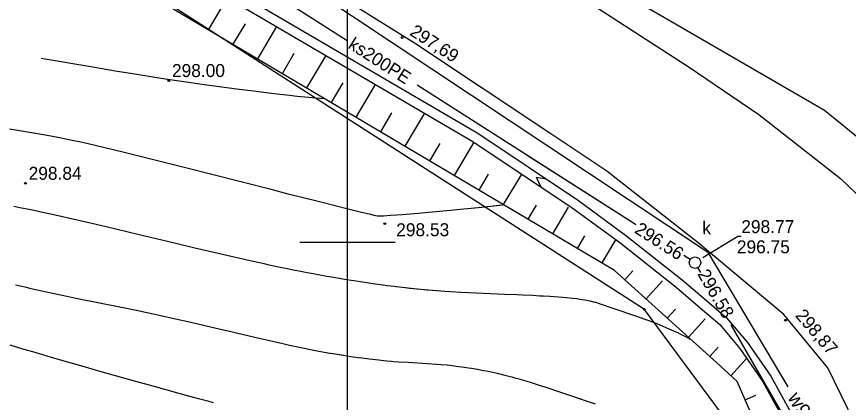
# Model space of a CAD drawing. Extents: x 7477803 to 7478145, y 5500698 to 5500984.
# Drawn here: x 7477982.63 to 7478026.29, y 5500841.6 to 5500861.83 of the extents above; entities that cross this region are included whole.
import ezdxf

# ---------------------------------------------------------------- set-up
doc = ezdxf.new("R2010")
doc.units = 0
for name, color, linetype in [('203-Punkt załamania granicy działki nie stabilizowany', 7, 'Continuous'), ('eNN', 7, 'Continuous'), ('gr_dzialki', 7, 'Continuous'), ('gr_klasy', 7, 'Continuous'), ('jezdnia', 7, 'Continuous'), ('k', 7, 'Continuous'), ('k_elem_naziemne', 7, 'Continuous'), ('k_opis', 7, 'Continuous'), ('k_rzedne', 7, 'Continuous'), ('pkt_wys', 7, 'Continuous'), ('robocza49', 7, 'Continuous'), ('rowy', 7, 'Continuous'), ('skarp_wypel', 7, 'Continuous'), ('skarpa_gora', 7, 'Continuous'), ('w', 7, 'Continuous'), ('w_opis', 7, 'Continuous'), ('warst_ciagla', 7, 'Continuous'), ('warst_pogrub', 7, 'Continuous'), ('warst_przeryw', 7, 'Continuous')]:
    doc.layers.add(name, color=color, linetype=linetype)

# ---------------------------------------------------------------- blocks, each defined once
blk = doc.blocks.new('203')
blk.add_circle((0, 0), 0.045)
blk = doc.blocks.new('506_5_1')
at = {"layer": 'k_elem_naziemne'}
blk.add_circle((0, 0), 0.3, dxfattribs=at)
blk = doc.blocks.new('801_3')
at = {"layer": 'pkt_wys'}
blk.add_circle((0, 0), 0.045, dxfattribs=at)
blk.add_circle((0, 0), 0.045, dxfattribs=at)
blk = doc.blocks.new('801_5_2')
at = {"layer": 'pkt_wys'}
blk.add_circle((0, 0), 0.05, dxfattribs=at)
blk.add_circle((0, 0), 0.05, dxfattribs=at)

msp = doc.modelspace()

# ---------------------------------------------------------------- linework, layer by layer
at = {"layer": 'eNN'}
msp.add_lwpolyline([(7478044.292, 5500829.332), (7478043.979, 5500830.08), (7478036.967, 5500842.126), (7478033.374, 5500847.92), (7478030.266, 5500851.792), (7478027.179, 5500855.154), (7478025.031, 5500856.9), (7478008.369, 5500866.572), (7477997.07, 5500873.297), (7477990.438, 5500877.31), (7477980.374, 5500883.358), (7477966.627, 5500891.122), (7477956.111, 5500897.36), (7477948.099, 5500902.324), (7477944.454, 5500904.573)], dxfattribs=at)
at = {"layer": 'gr_dzialki'}
for points in [[(7478015.58, 5500846.47), (7477983.69, 5500866.96)], [(7478021.72, 5500838.18), (7478015.58, 5500846.47)]]:
    msp.add_lwpolyline(points, dxfattribs=at)
at = {"layer": 'gr_klasy'}
for points in [[(7478015.58, 5500846.47), (7477983.69, 5500866.96)], [(7478021.72, 5500838.18), (7478015.58, 5500846.47)]]:
    msp.add_lwpolyline(points, dxfattribs=at)
at = {"layer": 'jezdnia'}
for points in [[(7478010.61, 5500855.711), (7478003.516, 5500860.43), (7477987.535, 5500870.412)], [(7478012.783, 5500862.5), (7478017.927, 5500859.186), (7478021.58, 5500856.7), (7478025.873, 5500853.334), (7478028.356, 5500850.967), (7478030.699, 5500848.349), (7478032.422, 5500845.441), (7478033.114, 5500843.932), (7478033.826, 5500841.963), (7478034.518, 5500839.904), (7478035.522, 5500835.985), (7478035.876, 5500832.755), (7478035.757, 5500831.475), (7478035.341, 5500827.995), (7478034.495, 5500824.894), (7478032.649, 5500820.712), (7478031.642, 5500818.53)], [(7478008.149, 5500811.845), (7478011.769, 5500811.909), (7478014.098, 5500812.451), (7478017.047, 5500813.895), (7478021.153, 5500817.039), (7478024.239, 5500820.732), (7478026.136, 5500823.914), (7478027.522, 5500827.266), (7478028.159, 5500830.207), (7478028.284, 5500834.367), (7478027.822, 5500836.806), (7478026.257, 5500841.255), (7478025.204, 5500843.403), (7478022.901, 5500846.211), (7478018.407, 5500849.956), (7478013.603, 5500853.721), (7478010.61, 5500855.711)]]:
    msp.add_lwpolyline(points, dxfattribs=at)
at = {"layer": 'k'}
for p, q in [((7478018.542, 5500848.401), (7478018.389, 5500848.666)), ((7478018.464, 5500848.536), (7478018.389, 5500848.666)), ((7478021.173, 5500843.859), (7478020.132, 5500845.657)), ((7478024.88, 5500837.459), (7478020.15, 5500845.626))]:
    msp.add_line(p, q, dxfattribs=at)
for points in [[(7477999.978, 5500860.567), (7477987.079, 5500868.79)], [(7478015.054, 5500850.956), (7478003.646, 5500858.229)], [(7478015.054, 5500850.956), (7478009.436, 5500854.538)], [(7478015.128, 5500850.909), (7478015.058, 5500850.953)], [(7478017.985, 5500849.087), (7478017.658, 5500849.296)], [(7478017.985, 5500849.087), (7478017.722, 5500849.255)]]:
    msp.add_lwpolyline(points, dxfattribs=at)
at = {"layer": 'k_rzedne'}
msp.add_lwpolyline([(7478020.666, 5500850.293), (7478020.486, 5500850.292), (7478018.654, 5500849.176)], dxfattribs=at)
at = {"layer": 'robocza49'}
for p, q in [((7478000, 5500750), (7478000, 5500973.047)), ((7477997.5, 5500850), (7478000, 5500850)), ((7478000, 5500850), (7478002.5, 5500850))]:
    msp.add_line(p, q, dxfattribs=at)
at = {"layer": 'rowy'}
for points in [[(7477993.882, 5500863.302), (7478006.843, 5500855.712), (7478012.127, 5500852.184), (7478014.592, 5500850.374), (7478017.571, 5500848.032), (7478018.72, 5500847.044), (7478019.889, 5500846.025), (7478020.984, 5500844.732), (7478022.21, 5500842.975), (7478023.266, 5500841.06)], [(7477993.629, 5500862.871), (7478006.577, 5500855.288), (7478011.84, 5500851.774), (7478014.289, 5500849.976), (7478017.253, 5500847.646), (7478018.393, 5500846.666), (7478019.532, 5500845.673), (7478020.588, 5500844.427), (7478021.784, 5500842.711), (7478022.816, 5500840.841)], [(7478010.445, 5500853.307), (7478009.897, 5500853.386), (7478010.167, 5500852.891)]]:
    msp.add_lwpolyline(points, dxfattribs=at)
at = {"layer": 'skarp_wypel'}
for p, q in [((7477992.709, 5500861.145), (7477993.705, 5500862.826)), ((7477996.548, 5500861.74), (7477996.553, 5500861.749)), ((7477993.999, 5500860.381), (7477994.636, 5500861.456)), ((7477995.29, 5500859.616), (7477996.293, 5500861.31)), ((7477996.58, 5500858.852), (7477997.207, 5500859.909)), ((7477997.871, 5500858.087), (7477998.882, 5500859.794)), ((7477999.161, 5500857.322), (7477999.777, 5500858.363)), ((7478000.452, 5500856.558), (7478001.471, 5500858.278)), ((7478001.742, 5500855.793), (7478002.333, 5500856.79)), ((7478003.032, 5500855.028), (7478004.06, 5500856.762)), ((7478005.613, 5500853.499), (7478006.644, 5500855.239)), ((7478004.323, 5500854.264), (7478004.863, 5500855.176)), ((7478006.904, 5500852.734), (7478007.394, 5500853.562)), ((7478008.194, 5500851.97), (7478009.125, 5500853.54)), ((7478009.485, 5500851.205), (7478009.925, 5500851.948)), ((7478010.775, 5500850.441), (7478011.605, 5500851.841)), ((7478012.066, 5500849.676), (7478012.456, 5500850.334)), ((7478013.356, 5500848.911), (7478014.074, 5500850.123)), ((7478014.558, 5500848.027), (7478014.979, 5500848.491)), ((7478015.671, 5500847.02), (7478016.525, 5500847.964)), ((7478016.783, 5500846.014), (7478017.217, 5500846.493)), ((7478017.895, 5500845.008), (7478018.776, 5500845.981)), ((7478019.008, 5500844.001), (7478019.455, 5500844.495)), ((7478020.12, 5500842.995), (7478020.948, 5500843.91)), ((7478020.875, 5500843.829), (7478020.948, 5500843.91)), ((7478020.869, 5500841.727), (7478021.423, 5500841.969))]:
    msp.add_line(p, q, dxfattribs=at)
at = {"layer": 'skarpa_gora'}
for points in [[(7478019.361, 5500843.679), (7478014.009, 5500848.521), (7477985, 5500865.71), (7477963.897, 5500877.826), (7477945.275, 5500888.626), (7477927.783, 5500899.247), (7477912.023, 5500908.9), (7477901.238, 5500913.008)], [(7478024.174, 5500834.162), (7478020.445, 5500842.698), (7478019.361, 5500843.679)]]:
    msp.add_lwpolyline(points, dxfattribs=at)
at = {"layer": 'w'}
msp.add_lwpolyline([(7478023.125, 5500842.409), (7478018.943, 5500849.443), (7477996.094, 5500864.625), (7477987.395, 5500870.305)], dxfattribs=at)
at = {"layer": 'warst_ciagla'}
for points in [[(7477998.803, 5500857.513), (7477998.521, 5500857.535), (7477997.944, 5500857.586), (7477997.354, 5500857.646), (7477996.955, 5500857.69), (7477996.148, 5500857.785), (7477994.926, 5500857.935), (7477994.314, 5500858.012), (7477993.397, 5500858.133), (7477992.486, 5500858.257), (7477991.28, 5500858.428), (7477990.681, 5500858.517), (7477989.881, 5500858.639), (7477989.472, 5500858.702), (7477988.836, 5500858.804), (7477987.801, 5500858.974), (7477986.637, 5500859.172), (7477983.919, 5500859.642)], [(7478018.003, 5500844.893), (7478017.839, 5500844.984), (7478017.726, 5500845.044), (7478017.492, 5500845.163), (7478017.372, 5500845.221), (7478017.129, 5500845.335), (7478016.886, 5500845.444), (7478016.725, 5500845.514), (7478016.412, 5500845.644), (7478016.245, 5500845.711), (7478015.926, 5500845.833), (7478015.629, 5500845.941), (7478015.085, 5500846.13), (7478014.04, 5500846.486), (7478013.23, 5500846.761), (7478013.03, 5500846.827), (7478012.927, 5500846.857), (7478012.758, 5500846.901), (7478012.63, 5500846.929), (7478012.56, 5500846.943), (7478012.446, 5500846.963), (7478012.319, 5500846.982), (7478012.13, 5500847.008), (7478012.027, 5500847.021), (7478011.805, 5500847.045), (7478011.474, 5500847.077), (7478011.294, 5500847.093), (7478010.851, 5500847.127), (7478010.611, 5500847.143), (7478010.272, 5500847.165), (7478010.094, 5500847.175), (7478009.721, 5500847.196), (7478009.189, 5500847.222), (7478008.908, 5500847.235), (7478008.239, 5500847.263), (7478006.757, 5500847.32), (7478005.953, 5500847.358), (7478005.396, 5500847.391), (7478005.112, 5500847.409), (7478004.679, 5500847.441), (7478004.238, 5500847.478), (7478003.64, 5500847.534), (7478003.336, 5500847.566), (7478002.718, 5500847.635), (7478002.439, 5500847.669), (7478002.063, 5500847.717), (7478001.873, 5500847.742), (7478001.442, 5500847.801), (7478001.115, 5500847.848), (7478000.674, 5500847.914), (7478000.451, 5500847.948), (7477999.945, 5500848.029), (7477999.258, 5500848.145), (7477998.909, 5500848.206), (7477998.203, 5500848.335), (7477997.885, 5500848.395), (7477997.456, 5500848.478), (7477997.24, 5500848.521), (7477996.75, 5500848.619), (7477996.379, 5500848.696), (7477995.879, 5500848.801), (7477995.627, 5500848.855), (7477995.054, 5500848.981), (7477994.67, 5500849.066), (7477993.899, 5500849.242), (7477992.747, 5500849.51), (7477991.993, 5500849.689), (7477990.548, 5500850.034), (7477989.064, 5500850.388), (7477987.338, 5500850.797), (7477986.582, 5500850.974), (7477985.584, 5500851.206), (7477984.505, 5500851.451), (7477984.073, 5500851.547), (7477983.552, 5500851.658), (7477983.271, 5500851.715), (7477982.8, 5500851.807), (7477982.478, 5500851.868)], [(7478008.147, 5500851.946), (7478007.678, 5500851.888), (7478007.352, 5500851.851), (7478006.678, 5500851.781)], [(7478018.003, 5500844.893), (7478017.839, 5500844.984), (7478017.726, 5500845.044), (7478017.492, 5500845.163), (7478017.372, 5500845.221), (7478017.129, 5500845.335), (7478016.886, 5500845.444), (7478016.725, 5500845.514), (7478016.412, 5500845.644), (7478016.245, 5500845.711), (7478015.926, 5500845.833), (7478015.629, 5500845.941), (7478015.085, 5500846.13), (7478014.04, 5500846.486), (7478013.23, 5500846.761), (7478013.03, 5500846.827), (7478012.927, 5500846.857), (7478012.758, 5500846.901), (7478012.63, 5500846.929), (7478012.56, 5500846.943), (7478012.446, 5500846.963), (7478012.319, 5500846.982), (7478012.13, 5500847.008), (7478012.027, 5500847.021), (7478011.805, 5500847.045), (7478011.474, 5500847.077), (7478011.294, 5500847.093), (7478010.851, 5500847.127), (7478010.611, 5500847.143), (7478010.272, 5500847.165), (7478010.094, 5500847.175), (7478009.721, 5500847.196), (7478009.189, 5500847.222), (7478008.908, 5500847.235), (7478008.239, 5500847.263), (7478006.757, 5500847.32), (7478005.953, 5500847.358), (7478005.396, 5500847.391), (7478005.112, 5500847.409), (7478004.679, 5500847.441), (7478004.45, 5500847.46), (7478004.142, 5500847.486), (7478003.987, 5500847.501), (7478003.674, 5500847.531), (7478003.25, 5500847.575), (7478003.037, 5500847.599), (7478002.549, 5500847.656)]]:
    msp.add_lwpolyline(points, dxfattribs=at)
at = {"layer": 'warst_pogrub'}
msp.add_lwpolyline([(7477992.967, 5500841.575), (7477992.736, 5500841.636), (7477992.173, 5500841.787), (7477991.215, 5500842.048), (7477989.725, 5500842.459), (7477988.888, 5500842.693), (7477987.067, 5500843.206), (7477986.128, 5500843.473), (7477984.755, 5500843.868), (7477983.488, 5500844.239), (7477982.963, 5500844.395), (7477982.3, 5500844.594)], dxfattribs=at)
at = {"layer": 'warst_przeryw'}
for points in [[(7478008.147, 5500851.946), (7478007.936, 5500851.919), (7478007.5, 5500851.868), (7478007.047, 5500851.819), (7478006.11, 5500851.726), (7478005.403, 5500851.66), (7478004.081, 5500851.541), (7478003.513, 5500851.492), (7478002.868, 5500851.439), (7478002.595, 5500851.418), (7478002.246, 5500851.393), (7478001.894, 5500851.372), (7478001.766, 5500851.366), (7478001.678, 5500851.365), (7478001.637, 5500851.366), (7478001.576, 5500851.371), (7478001.466, 5500851.389), (7478001.397, 5500851.403), (7478001.214, 5500851.445), (7478000.795, 5500851.545), (7477999.955, 5500851.753), (7477999.414, 5500851.888), (7477998.452, 5500852.13), (7477996.887, 5500852.526), (7477995.984, 5500852.756), (7477992.94, 5500853.53), (7477991.42, 5500853.915), (7477990.03, 5500854.264), (7477988.408, 5500854.665), (7477987.696, 5500854.838), (7477986.751, 5500855.063), (7477986.379, 5500855.15), (7477985.928, 5500855.254), (7477985.722, 5500855.3), (7477985.306, 5500855.391), (7477984.798, 5500855.496), (7477984.52, 5500855.549), (7477984.046, 5500855.633), (7477983.098, 5500855.792), (7477982.259, 5500855.928)], [(7477982.57, 5500847.769), (7477982.811, 5500847.71), (7477983.144, 5500847.631), (7477983.316, 5500847.591), (7477983.717, 5500847.499), (7477984.352, 5500847.358), (7477984.352, 5500847.358), (7477985.263, 5500847.165), (7477985.745, 5500847.066), (7477988.129, 5500846.587), (7477988.993, 5500846.407), (7477990.195, 5500846.149), (7477990.817, 5500846.013), (7477991.778, 5500845.797), (7477993.109, 5500845.492), (7477993.796, 5500845.331), (7477995.204, 5500844.999), (7477995.912, 5500844.835), (7477996.612, 5500844.677), (7477996.957, 5500844.601), (7477997.299, 5500844.528), (7477997.746, 5500844.436), (7477997.967, 5500844.392), (7477998.404, 5500844.308), (7477998.973, 5500844.203), (7477999.252, 5500844.155), (7477999.867, 5500844.054), (7478000.169, 5500844.008), (7478000.563, 5500843.952), (7478000.757, 5500843.925), (7478001.14, 5500843.877), (7478001.638, 5500843.82), (7478001.882, 5500843.795), (7478002.062, 5500843.778), (7478002.3, 5500843.758), (7478002.417, 5500843.748), (7478002.679, 5500843.729), (7478003.189, 5500843.697), (7478004.177, 5500843.641), (7478004.662, 5500843.608), (7478004.903, 5500843.588), (7478005.224, 5500843.557), (7478005.384, 5500843.539), (7478005.704, 5500843.501), (7478006.13, 5500843.443), (7478006.342, 5500843.411), (7478006.501, 5500843.386), (7478006.713, 5500843.35), (7478006.819, 5500843.331), (7478007.056, 5500843.288), (7478007.372, 5500843.225), (7478007.53, 5500843.192), (7478007.845, 5500843.123), (7478008.264, 5500843.023), (7478008.473, 5500842.97), (7478008.63, 5500842.929), (7478008.838, 5500842.872), (7478008.943, 5500842.843), (7478009.177, 5500842.776), (7478009.643, 5500842.635), (7478010.106, 5500842.487), (7478010.412, 5500842.387), (7478011.019, 5500842.184), (7478012.285, 5500841.758)], [(7477999.077, 5500844.185), (7477999.343, 5500844.139), (7477999.694, 5500844.081), (7477999.867, 5500844.054), (7478000.169, 5500844.008), (7478000.563, 5500843.952), (7478000.757, 5500843.925), (7478001.14, 5500843.877), (7478001.638, 5500843.82), (7478001.882, 5500843.795), (7478002.062, 5500843.778), (7478002.3, 5500843.758), (7478002.417, 5500843.748), (7478002.679, 5500843.729), (7478003.189, 5500843.697), (7478004.177, 5500843.641), (7478004.662, 5500843.608), (7478004.903, 5500843.588), (7478005.224, 5500843.557), (7478005.384, 5500843.539), (7478005.704, 5500843.501), (7478006.13, 5500843.443), (7478006.342, 5500843.411), (7478006.501, 5500843.386), (7478006.713, 5500843.35), (7478006.819, 5500843.331), (7478007.056, 5500843.288), (7478007.372, 5500843.225), (7478007.53, 5500843.192), (7478007.845, 5500843.123), (7478008.264, 5500843.023), (7478008.473, 5500842.97), (7478008.63, 5500842.929), (7478008.838, 5500842.872), (7478008.943, 5500842.843), (7478009.177, 5500842.776), (7478009.643, 5500842.635), (7478010.106, 5500842.487), (7478010.412, 5500842.387), (7478011.019, 5500842.184), (7478012.992, 5500841.519)]]:
    msp.add_lwpolyline(points, dxfattribs=at)

# ---------------------------------------------------------------- block references
at = {"layer": '203-Punkt załamania granicy działki nie stabilizowany'}
msp.add_blockref('203', (7478015.58, 5500846.47), dxfattribs=at)
at = {"layer": 'k_elem_naziemne', "rotation": 0.0626175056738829}
msp.add_blockref('506_5_1', (7478018.238, 5500848.926), dxfattribs=at)
at = {"layer": 'pkt_wys', "rotation": 0.0626175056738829}
for name, p in [('801_5_2', (7478002.875, 5500860.739)), ('801_3', (7477990.618, 5500858.476)), ('801_3', (7477983.094, 5500853.087)), ('801_3', (7478001.956, 5500850.968)), ('801_5_2', (7478022.992, 5500845.901))]:
    msp.add_blockref(name, p, dxfattribs=at)

# ---------------------------------------------------------------- texts
at = {"layer": 'k_elem_naziemne'}
msp.add_text('k', height=0.68, rotation=0.0626, dxfattribs=at).set_placement((7478018.621, 5500850.411))
at = {"layer": 'k_opis'}
msp.add_text('ks200PE', height=0.68, rotation=327.4817, dxfattribs=at).set_placement((7477999.978, 5500860.21))
at = {"layer": 'k_rzedne'}
for s, rotation, p in [('296.56', 327.4817, (7478015.013, 5500850.521)), ('298.77', 0.0626, (7478020.666, 5500850.473)), ('296.75', 0.0626, (7478020.434, 5500849.414)), ('296.58', 300.0796, (7478018.343, 5500848.336))]:
    msp.add_text(s, height=0.68, rotation=rotation, dxfattribs=at).set_placement(p)
at = {"layer": 'pkt_wys'}
for s, rotation, p in [('297,69', 327.2853, (7478003.216, 5500860.893)), ('298.00', 0.0626, (7477990.787, 5500858.66)), ('298.84', 0.0626, (7477983.263, 5500853.272)), ('298.53', 0.0626, (7478002.556, 5500850.31)), ('298,87', 310.5233, (7478023.463, 5500846.132))]:
    msp.add_text(s, height=0.68, rotation=rotation, dxfattribs=at).set_placement(p)
at = {"layer": 'w_opis'}
msp.add_text('w90PE', height=0.75, rotation=300.5443, dxfattribs=at).set_placement((7478023.07, 5500841.852))

doc.saveas('drawing.dxf')
